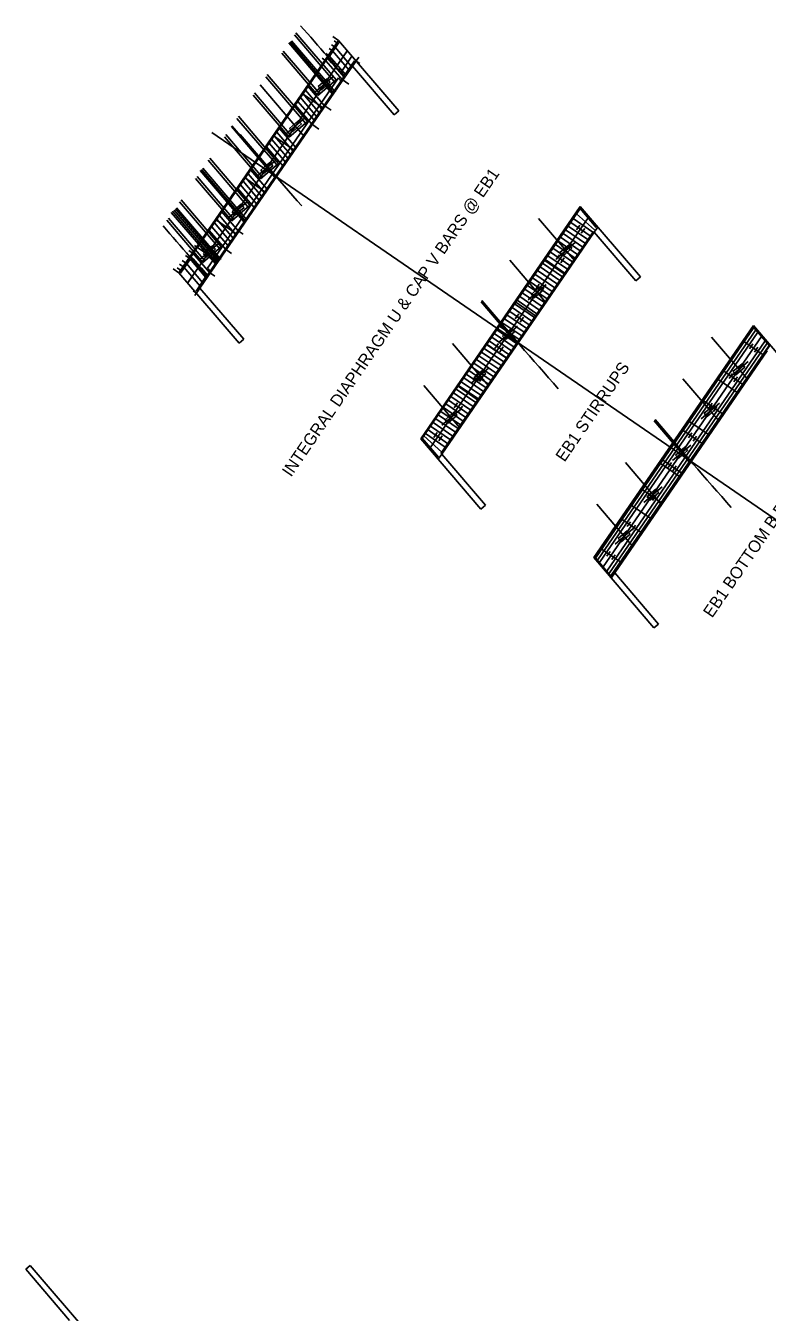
# Model space of a CAD drawing. Extents: x 2378999 to 2381348, y 331302 to 333122.
# Drawn here: x 2379237.2 to 2379360.9, y 331618.1 to 331832.8 of the extents above; entities that cross this region are included whole.
import ezdxf

# ---------------------------------------------------------------- set-up
doc = ezdxf.new("R2010")
doc.units = 0
for name, color, linetype in [('Arrowhead Terminators', 7, 'Continuous'), ('Dimension Lines', 7, 'Continuous'), ('Dimension Lines CELL', 7, 'Continuous'), ('Mis Work Point CELL', 7, 'Continuous'), ('P_SMU_Approach_Slab', 7, 'Continuous'), ('P_SMU_Bent_Cap', 7, 'Continuous'), ('P_SMU_Concrete_Barrier_Rail', 7, 'Continuous'), ('P_SMU_D_Deck_Outline', 7, 'Continuous'), ('P_SMU_Deck', 7, 'Continuous'), ('P_SMU_Girder_Concrete', 7, 'Continuous'), ('P_SMU_Mis_L_Lines', 7, 'Continuous'), ('P_SMU_Mis_Long_Chord', 7, 'Continuous'), ('P_SMU_Mis_Short_Chord', 7, 'Continuous'), ('P_SMU_Rebar_B_Bar', 7, 'Continuous'), ('P_SMU_Rebar_K_Bar', 7, 'Continuous'), ('P_SMU_Rebar_U_Bar', 7, 'Continuous'), ('Plan Sheet CELL', 7, 'Continuous'), ('Rebar Lines', 7, 'Continuous'), ('Scratch_Level_0', 7, 'Continuous'), ('Sup Concrete Slab Lines', 7, 'Continuous'), ('Text', 7, 'Continuous')]:
    doc.layers.add(name, color=color, linetype=linetype)

msp = doc.modelspace()

# ---------------------------------------------------------------- linework, layer by layer
at = {"layer": 'Arrowhead Terminators'}
for p, q in [((2379332.2, 331743.99), (2379358.62, 331782.44)), ((2379332.52, 331743.61), (2379358.94, 331782.07)), ((2379332.86, 331743.22), (2379359.28, 331781.67)), ((2379360.51, 331780.23), (2379334.09, 331741.78)), ((2379360.85, 331779.84), (2379334.43, 331741.38)), ((2379361.17, 331779.46), (2379334.75, 331741.01))]:
    msp.add_line(p, q, dxfattribs=at)
at = {"layer": 'Dimension Lines'}
for p, q in [((2379288.36, 331828.62), (2379287.76, 331829.03)), ((2379288.78, 331829.24), (2379288.19, 331829.65)), ((2379289.21, 331829.86), (2379288.61, 331830.27)), ((2379287.23, 331826.97), (2379286.63, 331827.38)), ((2379287.79, 331827.8), (2379287.2, 331828.2)), ((2379291.67, 331826.08), (2379292.71, 331827.59)), ((2379292.25, 331826.93), (2379292.9, 331826.49)), ((2379289.92, 331823.82), (2379291.05, 331823.05)), ((2379286.96, 331819.51), (2379288.09, 331818.74)), ((2379284.83, 331816.42), (2379286.07, 331815.57)), ((2379331.78, 331798.35), (2379328.49, 331800.62)), ((2379329.06, 331801.45), (2379332.05, 331798.75)), ((2379329.63, 331802.29), (2379332.32, 331799.14)), ((2379330.51, 331796.5), (2379327.21, 331798.76)), ((2379330.93, 331797.12), (2379327.64, 331799.38)), ((2379329.23, 331794.64), (2379325.94, 331796.91)), ((2379329.66, 331795.26), (2379326.36, 331797.53)), ((2379330.08, 331795.88), (2379326.79, 331798.15)), ((2379264.54, 331793.96), (2379263.82, 331794.45)), ((2379265.11, 331794.78), (2379264.39, 331795.28)), ((2379327.54, 331792.17), (2379324.24, 331794.44)), ((2379328.38, 331793.41), (2379325.09, 331795.67)), ((2379328.81, 331794.03), (2379325.51, 331796.29)), ((2379263.13, 331791.9), (2379262.4, 331792.39)), ((2379263.55, 331792.51), (2379262.83, 331793.01)), ((2379263.98, 331793.13), (2379263.25, 331793.63)), ((2379326.26, 331790.32), (2379322.96, 331792.58)), ((2379326.69, 331790.94), (2379323.39, 331793.2)), ((2379327.11, 331791.55), (2379323.81, 331793.82)), ((2379267.8, 331791.63), (2379268.7, 331791.01)), ((2379324.99, 331788.46), (2379321.69, 331790.73)), ((2379325.41, 331789.08), (2379322.11, 331791.35)), ((2379325.84, 331789.7), (2379322.54, 331791.96)), ((2379265.64, 331788.19), (2379265.11, 331788.56)), ((2379266.23, 331789.04), (2379265.36, 331787.79)), ((2379323.29, 331785.99), (2379319.99, 331788.26)), ((2379323.71, 331786.61), (2379320.42, 331788.87)), ((2379324.14, 331787.23), (2379320.84, 331789.49)), ((2379321.59, 331783.52), (2379318.29, 331785.78)), ((2379322.01, 331784.14), (2379318.72, 331786.4)), ((2379322.44, 331784.75), (2379319.14, 331787.02)), ((2379322.86, 331785.37), (2379319.57, 331787.64)), ((2379320.32, 331781.66), (2379317.02, 331783.93)), ((2379320.74, 331782.28), (2379317.44, 331784.55)), ((2379318.62, 331779.19), (2379315.32, 331781.46)), ((2379319.04, 331779.81), (2379315.74, 331782.07)), ((2379319.47, 331780.43), (2379316.17, 331782.69)), ((2379319.89, 331781.05), (2379316.59, 331783.31)), ((2379317.34, 331777.34), (2379314.05, 331779.6)), ((2379318.19, 331778.57), (2379314.89, 331780.84)), ((2379315.64, 331774.86), (2379312.35, 331777.13)), ((2379316.07, 331775.48), (2379312.77, 331777.75)), ((2379316.49, 331776.1), (2379313.2, 331778.36)), ((2379316.92, 331776.72), (2379313.62, 331778.98)), ((2379314.79, 331773.63), (2379311.5, 331775.89)), ((2379315.22, 331774.25), (2379311.92, 331776.51)), ((2379312.67, 331770.54), (2379309.37, 331772.8)), ((2379313.1, 331771.15), (2379309.8, 331773.42)), ((2379313.52, 331771.77), (2379310.22, 331774.04)), ((2379313.94, 331772.39), (2379310.65, 331774.66)), ((2379311.4, 331768.68), (2379308.1, 331770.95)), ((2379311.82, 331769.3), (2379308.52, 331771.57)), ((2379312.25, 331769.92), (2379308.95, 331772.18)), ((2379309.7, 331766.21), (2379306.4, 331768.47)), ((2379310.12, 331766.83), (2379306.83, 331769.09)), ((2379310.55, 331767.45), (2379307.25, 331769.71)), ((2379308.42, 331764.35), (2379305.13, 331766.62)), ((2379308.85, 331764.97), (2379305.55, 331767.24)), ((2379309.27, 331765.59), (2379305.98, 331767.86)), ((2379303.58, 331764.37), (2379306.58, 331761.66)), ((2379307.15, 331762.5), (2379303.85, 331764.77)), ((2379308, 331763.74), (2379304.7, 331766)), ((2379303.31, 331763.98), (2379306, 331760.83))]:
    msp.add_line(p, q, dxfattribs=at)
at = {"layer": 'Dimension Lines CELL'}
msp.add_line((2379454.16, 331687.23), (2379268.2, 331815), dxfattribs=at)
at = {"layer": 'Mis Work Point CELL'}
for p, q in [((2379264.18, 331789.9), (2379290.8, 331828.64)), ((2379304.51, 331762.19), (2379331.12, 331800.93)), ((2379333.38, 331742.36), (2379359.99, 331781.1))]:
    msp.add_line(p, q, dxfattribs=at)
at = {"layer": 'P_SMU_Approach_Slab'}
msp.add_line((2379267.49, 331792.36), (2379289.32, 331824.13), dxfattribs=at)
for radius, start, end in [(7061.33, 221.090701, 221.097683), (7098.67, 221.168161, 221.175103)]:
    msp.add_arc((2384611.23, 336465.21), radius, start, end, dxfattribs=at)
at = {"layer": 'P_SMU_Bent_Cap'}
for p, q in [((2379288.46, 331824.32), (2379285.42, 331821.73)), ((2379283.68, 331817.36), (2379280.63, 331814.76)), ((2379278.89, 331810.39), (2379275.85, 331807.79)), ((2379274.1, 331803.42), (2379271.06, 331800.82)), ((2379269.31, 331796.45), (2379266.27, 331793.85)), ((2379328.79, 331796.62), (2379325.75, 331794.02)), ((2379324, 331789.65), (2379320.96, 331787.05)), ((2379319.22, 331782.68), (2379316.17, 331780.08)), ((2379314.43, 331775.71), (2379311.39, 331773.11)), ((2379357.66, 331776.78), (2379354.62, 331774.19)), ((2379309.64, 331768.74), (2379306.6, 331766.15)), ((2379352.87, 331769.82), (2379349.83, 331767.22)), ((2379348.08, 331762.85), (2379345.04, 331760.25)), ((2379343.3, 331755.88), (2379340.25, 331753.28)), ((2379338.51, 331748.91), (2379335.47, 331746.31))]:
    msp.add_line(p, q, dxfattribs=at)
at = {"layer": 'P_SMU_Concrete_Barrier_Rail'}
for radius, start, end in [(7060.38, 221.00405, 221.059373), (7060.38, 221.059373, 221.095684), (7099.63, 221.085985, 221.140982), (7099.63, 221.140982, 221.177079)]:
    msp.add_arc((2384611.23, 336465.21), radius, start, end, dxfattribs=at)
at = {"layer": 'P_SMU_D_Deck_Outline'}
for p, q in [((2379287.46, 331823.96), (2379285.94, 331822.66)), ((2379286.43, 331822.09), (2379285.94, 331822.66)), ((2379287.95, 331823.39), (2379286.43, 331822.09)), ((2379287.95, 331823.39), (2379287.46, 331823.96)), ((2379282.67, 331816.99), (2379281.15, 331815.69)), ((2379281.64, 331815.12), (2379281.15, 331815.69)), ((2379283.16, 331816.42), (2379281.64, 331815.12)), ((2379283.16, 331816.42), (2379282.67, 331816.99)), ((2379277.88, 331810.02), (2379276.36, 331808.72)), ((2379278.37, 331809.45), (2379276.85, 331808.15)), ((2379278.37, 331809.45), (2379277.88, 331810.02)), ((2379276.85, 331808.15), (2379276.36, 331808.72)), ((2379273.1, 331803.05), (2379271.58, 331801.76)), ((2379273.58, 331802.48), (2379273.1, 331803.05)), ((2379272.06, 331801.18), (2379271.58, 331801.76)), ((2379273.58, 331802.48), (2379272.06, 331801.18)), ((2379268.31, 331796.09), (2379266.79, 331794.79)), ((2379267.28, 331794.22), (2379266.79, 331794.79)), ((2379268.8, 331795.52), (2379267.28, 331794.22)), ((2379268.8, 331795.52), (2379268.31, 331796.09)), ((2379327.79, 331796.25), (2379326.27, 331794.95)), ((2379326.75, 331794.38), (2379326.27, 331794.95)), ((2379328.27, 331795.68), (2379326.75, 331794.38)), ((2379328.27, 331795.68), (2379327.79, 331796.25)), ((2379323, 331789.28), (2379321.48, 331787.99)), ((2379321.97, 331787.42), (2379321.48, 331787.99)), ((2379323.49, 331788.71), (2379321.97, 331787.42)), ((2379323.49, 331788.71), (2379323, 331789.28)), ((2379318.21, 331782.32), (2379316.69, 331781.02)), ((2379318.7, 331781.75), (2379317.18, 331780.45)), ((2379318.7, 331781.75), (2379318.21, 331782.32)), ((2379317.18, 331780.45), (2379316.69, 331781.02)), ((2379313.42, 331775.35), (2379311.9, 331774.05)), ((2379313.91, 331774.78), (2379313.42, 331775.35)), ((2379356.66, 331776.42), (2379355.13, 331775.12)), ((2379355.62, 331774.55), (2379355.13, 331775.12)), ((2379357.14, 331775.85), (2379355.62, 331774.55)), ((2379357.14, 331775.85), (2379356.66, 331776.42)), ((2379312.39, 331773.48), (2379311.9, 331774.05)), ((2379313.91, 331774.78), (2379312.39, 331773.48)), ((2379351.87, 331769.45), (2379350.35, 331768.15)), ((2379352.35, 331768.88), (2379350.83, 331767.58)), ((2379352.35, 331768.88), (2379351.87, 331769.45)), ((2379308.64, 331768.38), (2379307.12, 331767.08)), ((2379307.6, 331766.51), (2379307.12, 331767.08)), ((2379309.12, 331767.81), (2379307.6, 331766.51)), ((2379309.12, 331767.81), (2379308.64, 331768.38)), ((2379350.83, 331767.58), (2379350.35, 331768.15)), ((2379347.08, 331762.48), (2379345.56, 331761.18)), ((2379347.57, 331761.91), (2379347.08, 331762.48)), ((2379346.05, 331760.61), (2379345.56, 331761.18)), ((2379347.57, 331761.91), (2379346.05, 331760.61)), ((2379342.29, 331755.51), (2379340.77, 331754.22)), ((2379341.26, 331753.65), (2379340.77, 331754.22)), ((2379342.78, 331754.94), (2379341.26, 331753.65)), ((2379342.78, 331754.94), (2379342.29, 331755.51)), ((2379337.5, 331748.55), (2379335.98, 331747.25)), ((2379336.47, 331746.68), (2379335.98, 331747.25)), ((2379337.99, 331747.98), (2379336.47, 331746.68)), ((2379337.99, 331747.98), (2379337.5, 331748.55))]:
    msp.add_line(p, q, dxfattribs=at)
at = {"layer": 'P_SMU_Deck'}
for p, q in [((2379288.61, 331823.52), (2379281.98, 331831.28)), ((2379288.92, 331823.79), (2379282.22, 331831.63)), ((2379286.2, 331821.46), (2379280.12, 331828.58)), ((2379288.62, 331821.51), (2379281.27, 331830.12)), ((2379288.84, 331821.7), (2379281.49, 331830.31)), ((2379285.88, 331821.19), (2379279.87, 331828.22)), ((2379283.82, 331816.55), (2379277.19, 331824.31)), ((2379284.14, 331816.82), (2379277.43, 331824.66)), ((2379288.92, 331823.79), (2379285.88, 331821.19)), ((2379281.1, 331814.22), (2379275.09, 331821.25)), ((2379281.41, 331814.49), (2379275.33, 331821.61)), ((2379279.03, 331809.58), (2379272.4, 331817.34)), ((2379279.35, 331809.85), (2379272.64, 331817.7)), ((2379284.14, 331816.82), (2379281.1, 331814.22)), ((2379276.31, 331807.25), (2379270.3, 331814.28)), ((2379276.62, 331807.52), (2379270.54, 331814.64)), ((2379274.24, 331802.61), (2379267.61, 331810.37)), ((2379274.56, 331802.88), (2379267.86, 331810.73)), ((2379279.35, 331809.85), (2379276.31, 331807.25)), ((2379271.52, 331800.28), (2379265.51, 331807.31)), ((2379271.84, 331800.55), (2379265.76, 331807.67)), ((2379273.59, 331800.04), (2379266.24, 331808.64)), ((2379273.82, 331800.22), (2379266.46, 331808.83)), ((2379269.46, 331795.64), (2379262.82, 331803.4)), ((2379269.77, 331795.91), (2379263.07, 331803.76)), ((2379274.56, 331802.88), (2379271.52, 331800.28)), ((2379267.05, 331793.58), (2379260.97, 331800.7)), ((2379268.81, 331793.07), (2379261.45, 331801.67)), ((2379269.03, 331793.26), (2379261.67, 331801.86)), ((2379269.47, 331793.64), (2379262.12, 331802.24)), ((2379269.69, 331793.82), (2379262.34, 331802.43)), ((2379266.73, 331793.31), (2379260.72, 331800.35)), ((2379269.77, 331795.91), (2379266.73, 331793.31))]:
    msp.add_line(p, q, dxfattribs=at)
at = {"layer": 'P_SMU_Girder_Concrete'}
for p, q in [((2379329.02, 331798.73), (2379329.59, 331799.56)), ((2379329.3, 331799.15), (2379330.11, 331798.59)), ((2379329.83, 331798.18), (2379330.4, 331799)), ((2379325.62, 331793.79), (2379326.19, 331794.61)), ((2379325.91, 331794.2), (2379326.72, 331793.64)), ((2379326.43, 331793.23), (2379327, 331794.06)), ((2379322.23, 331788.84), (2379322.79, 331789.67)), ((2379322.51, 331789.26), (2379323.32, 331788.7)), ((2379323.04, 331788.29), (2379323.6, 331789.11)), ((2379318.83, 331783.9), (2379319.39, 331784.72)), ((2379319.11, 331784.31), (2379319.92, 331783.75)), ((2379319.64, 331783.34), (2379320.2, 331784.17)), ((2379315.43, 331778.95), (2379316, 331779.78)), ((2379315.71, 331779.37), (2379316.52, 331778.81)), ((2379316.24, 331778.4), (2379316.81, 331779.22)), ((2379357.89, 331778.9), (2379358.45, 331779.73)), ((2379358.17, 331779.31), (2379358.98, 331778.76)), ((2379358.7, 331778.34), (2379359.27, 331779.17)), ((2379312.03, 331774.01), (2379312.6, 331774.83)), ((2379312.32, 331774.42), (2379313.13, 331773.86)), ((2379312.84, 331773.45), (2379313.41, 331774.28)), ((2379354.49, 331773.96), (2379355.06, 331774.78)), ((2379354.77, 331774.37), (2379355.58, 331773.81)), ((2379355.3, 331773.4), (2379355.87, 331774.22)), ((2379308.63, 331769.06), (2379309.2, 331769.89)), ((2379308.92, 331769.47), (2379309.73, 331768.92)), ((2379309.45, 331768.51), (2379310.01, 331769.33)), ((2379351.09, 331769.01), (2379351.66, 331769.83)), ((2379351.38, 331769.42), (2379352.19, 331768.87)), ((2379351.9, 331768.45), (2379352.47, 331769.28)), ((2379305.24, 331764.12), (2379305.8, 331764.94)), ((2379305.52, 331764.53), (2379306.33, 331763.97)), ((2379306.05, 331763.56), (2379306.61, 331764.38)), ((2379347.7, 331764.07), (2379348.26, 331764.89)), ((2379347.98, 331764.48), (2379348.79, 331763.92)), ((2379348.51, 331763.51), (2379349.07, 331764.33)), ((2379344.3, 331759.12), (2379344.86, 331759.94)), ((2379344.58, 331759.53), (2379345.39, 331758.98)), ((2379345.11, 331758.56), (2379345.67, 331759.39)), ((2379340.9, 331754.17), (2379341.47, 331755)), ((2379341.18, 331754.59), (2379341.99, 331754.03)), ((2379341.71, 331753.62), (2379342.28, 331754.44)), ((2379337.5, 331749.23), (2379338.07, 331750.05)), ((2379337.79, 331749.64), (2379338.6, 331749.08)), ((2379338.31, 331748.67), (2379338.88, 331749.5)), ((2379334.11, 331744.28), (2379334.67, 331745.11)), ((2379334.39, 331744.7), (2379335.2, 331744.14)), ((2379334.92, 331743.73), (2379335.48, 331744.55))]:
    msp.add_line(p, q, dxfattribs=at)
at = {"layer": 'P_SMU_Mis_L_Lines'}
for p, q in [((2379288.4, 331821.32), (2379281.05, 331829.93)), ((2379283.61, 331814.35), (2379276.26, 331822.96)), ((2379278.82, 331807.38), (2379271.47, 331815.99)), ((2379274.04, 331800.41), (2379266.68, 331809.02)), ((2379269.25, 331793.45), (2379261.9, 331802.05)), ((2379328.73, 331793.61), (2379322.7, 331800.67)), ((2379323.94, 331786.64), (2379317.91, 331793.7)), ((2379319.15, 331779.68), (2379313.12, 331786.74)), ((2379314.36, 331772.71), (2379308.33, 331779.77)), ((2379357.6, 331773.78), (2379351.56, 331780.84)), ((2379309.58, 331765.74), (2379303.55, 331772.8)), ((2379352.81, 331766.81), (2379346.78, 331773.87)), ((2379348.02, 331759.84), (2379341.99, 331766.9)), ((2379343.23, 331752.87), (2379337.2, 331759.93)), ((2379338.44, 331745.91), (2379332.41, 331752.97))]:
    msp.add_line(p, q, dxfattribs=at)
at = {"layer": 'P_SMU_Mis_Long_Chord'}
for centre, start, end in [((2384611.23, 336465.21), 221.045135, 221.188495), ((2384651.56, 336437.5), 221.06156, 221.218654), ((2384680.43, 336417.67), 221.06156, 221.218654)]:
    msp.add_arc(centre, 7080, start, end, dxfattribs=at)
at = {"layer": 'P_SMU_Mis_Short_Chord'}
for p, q in [((2379272.59, 331798.61), (2379273.46, 331798.01)), ((2379270.47, 331795.52), (2379271.47, 331794.83))]:
    msp.add_line(p, q, dxfattribs=at)
at = {"layer": 'P_SMU_Rebar_B_Bar'}
for p, q in [((2379262.73, 331791.6), (2379289.34, 331830.34)), ((2379289.34, 331830.34), (2379299.38, 331818.59)), ((2379291.58, 331827.72), (2379289.77, 331825.07)), ((2379289.77, 331825.07), (2379290.44, 331824.3)), ((2379291.67, 331826.08), (2379289.88, 331823.48)), ((2379291.67, 331826.08), (2379298.62, 331817.94)), ((2379268.06, 331791.71), (2379289.88, 331823.48)), ((2379283.25, 331821.48), (2379286.82, 331819.03)), ((2379298.62, 331817.94), (2379299.38, 331818.59)), ((2379278.44, 331814.47), (2379282.01, 331812.02)), ((2379273.63, 331807.47), (2379277.2, 331805.01)), ((2379303.05, 331763.9), (2379329.67, 331802.63)), ((2379329.67, 331802.63), (2379339.7, 331790.89)), ((2379268.81, 331800.46), (2379272.38, 331798.01)), ((2379332, 331798.37), (2379332.58, 331799.22)), ((2379332, 331798.37), (2379306.55, 331761.34)), ((2379332, 331798.37), (2379338.94, 331790.24)), ((2379323.58, 331793.77), (2379327.15, 331791.32)), ((2379262.73, 331791.6), (2379272.76, 331779.85)), ((2379266.23, 331789.04), (2379268.06, 331791.71)), ((2379266.82, 331791.68), (2379267.5, 331790.9)), ((2379338.94, 331790.24), (2379339.7, 331790.89)), ((2379266.23, 331789.04), (2379273.52, 331780.5)), ((2379318.77, 331786.77), (2379322.34, 331784.31)), ((2379331.92, 331744.06), (2379358.54, 331782.8)), ((2379358.54, 331782.8), (2379368.57, 331771.05)), ((2379273.52, 331780.5), (2379272.76, 331779.85)), ((2379313.95, 331779.76), (2379317.53, 331777.31)), ((2379360.86, 331778.54), (2379335.42, 331741.5)), ((2379309.14, 331772.76), (2379312.71, 331770.3)), ((2379352.45, 331773.94), (2379356.02, 331771.49)), ((2379347.63, 331766.93), (2379351.21, 331764.48)), ((2379303.05, 331763.9), (2379313.09, 331752.15)), ((2379306.55, 331761.34), (2379305.97, 331760.48)), ((2379306.55, 331761.34), (2379313.85, 331752.8)), ((2379342.82, 331759.93), (2379346.39, 331757.47)), ((2379313.85, 331752.8), (2379313.09, 331752.15)), ((2379338.01, 331752.92), (2379341.58, 331750.47)), ((2379331.92, 331744.06), (2379341.96, 331732.32)), ((2379335.42, 331741.5), (2379334.83, 331740.65)), ((2379335.42, 331741.5), (2379342.72, 331732.96)), ((2379342.72, 331732.96), (2379341.96, 331732.32)), ((2379237.17, 331625.31), (2379237.93, 331625.95)), ((2379244.46, 331616.77), (2379237.17, 331625.31)), ((2379247.96, 331614.21), (2379237.93, 331625.95))]:
    msp.add_line(p, q, dxfattribs=at)
at = {"layer": 'P_SMU_Rebar_K_Bar'}
for p, q in [((2379287.77, 331827.62), (2379289.41, 331830)), ((2379290.7, 331828.49), (2379289.07, 331826.12)), ((2379291.99, 331826.98), (2379290.37, 331824.63)), ((2379262.99, 331791.55), (2379264.63, 331793.93)), ((2379264.28, 331790.04), (2379265.93, 331792.44)), ((2379265.57, 331788.53), (2379267.23, 331790.95))]:
    msp.add_line(p, q, dxfattribs=at)
at = {"layer": 'P_SMU_Rebar_U_Bar'}
for p, q in [((2379289.34, 331830.34), (2379288.39, 331830.99)), ((2379291.05, 331825.47), (2379288.36, 331828.62)), ((2379291.47, 331826.09), (2379288.78, 331829.24)), ((2379289.92, 331823.82), (2379287.23, 331826.97)), ((2379290.48, 331824.65), (2379287.79, 331827.8)), ((2379286.96, 331819.51), (2379284.27, 331822.66)), ((2379285.26, 331817.04), (2379282.57, 331820.19)), ((2379285.68, 331817.66), (2379282.99, 331820.81)), ((2379286.11, 331818.28), (2379283.42, 331821.42)), ((2379286.53, 331818.89), (2379283.84, 331822.04)), ((2379284.83, 331816.42), (2379282.14, 331819.57)), ((2379282.17, 331812.54), (2379279.48, 331815.69)), ((2379280.89, 331810.69), (2379278.2, 331813.84)), ((2379281.32, 331811.31), (2379278.63, 331814.46)), ((2379281.74, 331811.93), (2379279.05, 331815.07)), ((2379280.04, 331809.45), (2379277.35, 331812.6)), ((2379280.47, 331810.07), (2379277.78, 331813.22)), ((2379276.53, 331804.34), (2379273.84, 331807.49)), ((2379276.96, 331804.96), (2379274.27, 331808.11)), ((2379277.38, 331805.58), (2379274.69, 331808.72)), ((2379275.26, 331802.48), (2379272.57, 331805.63)), ((2379275.68, 331803.1), (2379272.99, 331806.25)), ((2379276.11, 331803.72), (2379273.42, 331806.87)), ((2379272.17, 331797.99), (2379269.48, 331801.14)), ((2379272.59, 331798.61), (2379269.9, 331801.76)), ((2379270.47, 331795.52), (2379267.78, 331798.66)), ((2379270.89, 331796.13), (2379268.2, 331799.28)), ((2379271.32, 331796.75), (2379268.63, 331799.9)), ((2379271.74, 331797.37), (2379269.05, 331800.52)), ((2379267.8, 331791.63), (2379265.11, 331794.78)), ((2379269.25, 331793.45), (2379265.33, 331796.14)), ((2379262.73, 331791.6), (2379261.78, 331792.25)), ((2379266.24, 331789.37), (2379263.55, 331792.51)), ((2379266.67, 331789.98), (2379263.98, 331793.13)), ((2379267.23, 331790.81), (2379264.54, 331793.96))]:
    msp.add_line(p, q, dxfattribs=at)
at = {"layer": 'Plan Sheet CELL'}
for p, q in [((2379278.97, 331807.6), (2379272.94, 331814.66)), ((2379319.3, 331779.89), (2379313.27, 331786.95)), ((2379348.17, 331760.06), (2379342.14, 331767.12))]:
    msp.add_line(p, q, dxfattribs=at)
at = {"layer": 'Rebar Lines'}
for p, q in [((2379327.92, 331800.1), (2379331.49, 331797.64)), ((2379324.53, 331795.15), (2379328.1, 331792.7)), ((2379321.13, 331790.2), (2379324.7, 331787.75)), ((2379317.73, 331785.26), (2379321.3, 331782.81)), ((2379314.33, 331780.31), (2379317.9, 331777.86)), ((2379356.79, 331780.26), (2379360.36, 331777.81)), ((2379310.93, 331775.37), (2379314.51, 331772.91)), ((2379353.39, 331775.32), (2379356.97, 331772.86)), ((2379307.54, 331770.42), (2379311.11, 331767.97)), ((2379350, 331770.37), (2379353.57, 331767.92)), ((2379304.14, 331765.48), (2379307.71, 331763.02)), ((2379346.6, 331765.43), (2379350.17, 331762.97)), ((2379343.2, 331760.48), (2379346.77, 331758.03)), ((2379339.8, 331755.54), (2379343.37, 331753.08)), ((2379336.41, 331750.59), (2379339.98, 331748.14)), ((2379333.01, 331745.64), (2379336.58, 331743.19))]:
    msp.add_line(p, q, dxfattribs=at)
at = {"layer": 'Scratch_Level_0'}
for p, q in [((2379264.77, 331794.28), (2379287.52, 331827.4)), ((2379267.48, 331791.17), (2379290.23, 331824.28)), ((2379303.19, 331763.8), (2379329.8, 331802.54)), ((2379331.86, 331798.46), (2379306.42, 331761.43)), ((2379332.13, 331744.07), (2379358.55, 331782.53)), ((2379358.55, 331782.53), (2379361.24, 331779.38)), ((2379361.24, 331779.38), (2379334.82, 331740.92)), ((2379332.13, 331744.07), (2379334.82, 331740.92))]:
    msp.add_line(p, q, dxfattribs=at)
for radius, start, end in [(7060.54, 221.061118, 221.094635), (7099.46, 221.142026, 221.175347)]:
    msp.add_arc((2384611.23, 336465.21), radius, start, end, dxfattribs=at)
at = {"layer": 'Text'}
for p, q in [((2379277.5, 331809.28), (2379277.5, 331809.28)), ((2379317.83, 331781.57), (2379317.83, 331781.57)), ((2379346.7, 331761.74), (2379346.7, 331761.74))]:
    msp.add_line(p, q, dxfattribs=at)

# ---------------------------------------------------------------- texts
at = {"layer": 'Sup Concrete Slab Lines'}
for s, p in [('INTEGRAL DIAPHRAGM U & CAP V BARS @ EB1', (2379281.42, 331757.4)), ('EB1 STIRRUPS', (2379327.04, 331759.9)), ('EB1 BOTTOM B BARS', (2379351.66, 331733.89))]:
    msp.add_text(s, height=2, rotation=55.5093, dxfattribs=at).set_placement(p)

doc.saveas('drawing.dxf')
